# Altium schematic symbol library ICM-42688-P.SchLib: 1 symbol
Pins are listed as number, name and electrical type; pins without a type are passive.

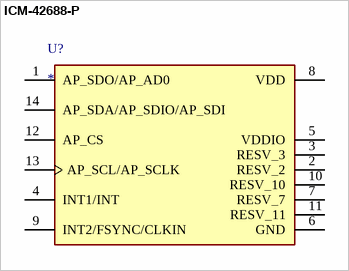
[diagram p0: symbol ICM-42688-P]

## ICM-42688-P
designator U?
Accelerometer, Gyroscope, 6 Axis Sensor Output; MP: ICM-42688-P
footprint PQFN50P300X250X97-14N
pins: 1 AP_SDO/AP_AD0, 2 RESV_2, 3 RESV_3, 4 INT1/INT, 5 VDDIO, 6 GND, 7 RESV_7, 8 VDD, 9 INT2/FSYNC/CLKIN, 10 RESV_10, 11 RESV_11, 12 AP_CS, 13 AP_SCL/AP_SCLK, 14 AP_SDA/AP_SDIO/AP_SDI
